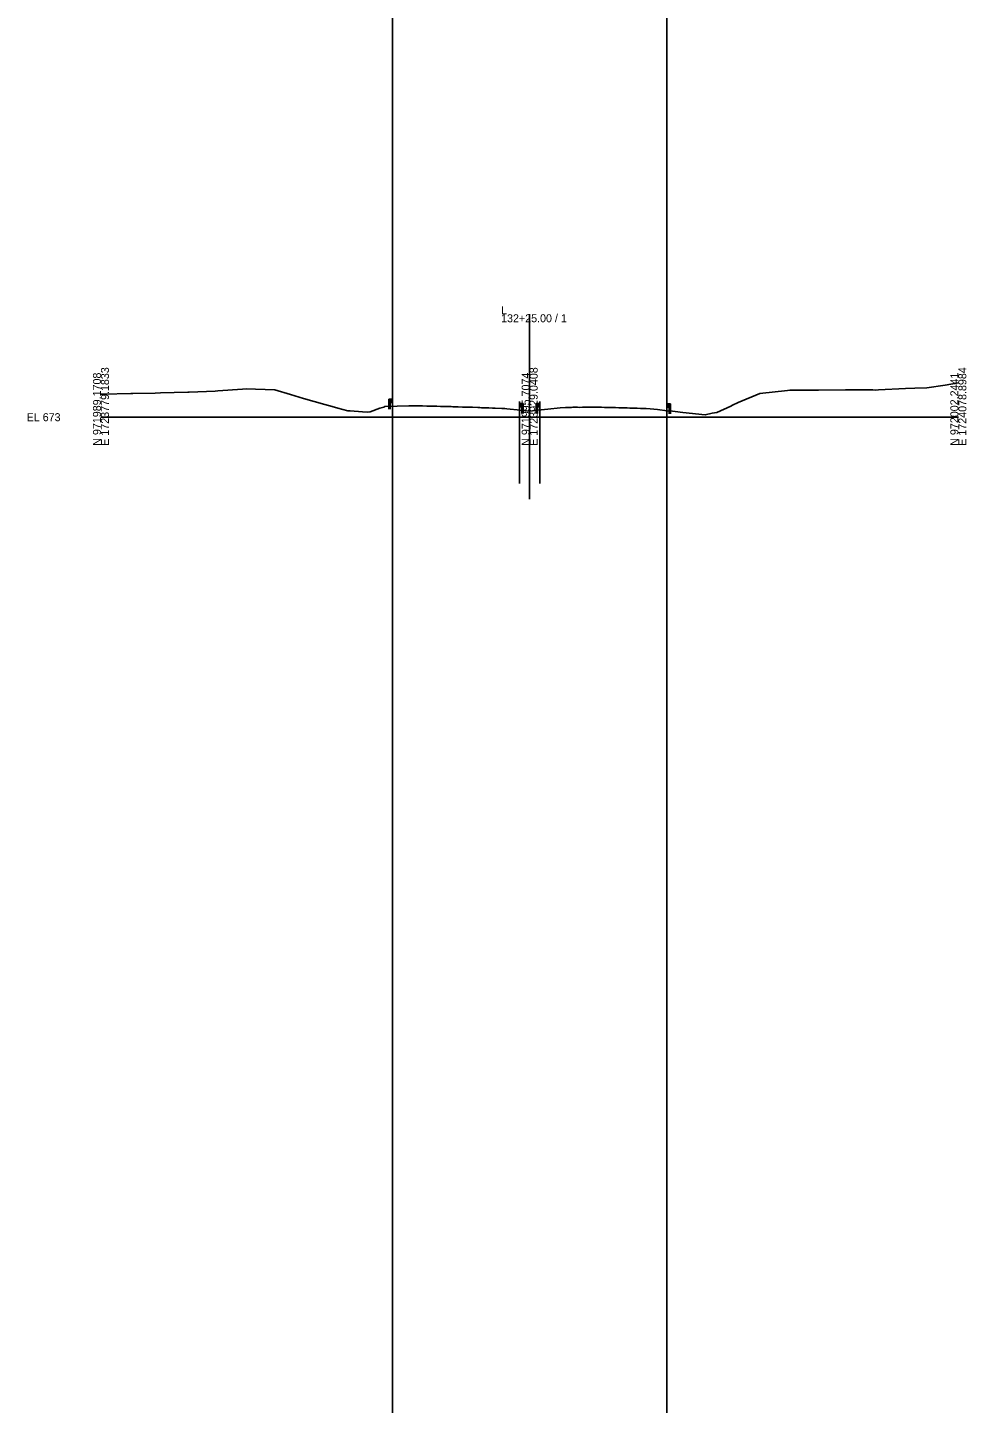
# Model space of a CAD drawing. Extents: x -26 to 303, y -29 to 15026.
# Drawn here: x -25.7 to 302.8, y 11654.8 to 12136.4 of the extents above; entities that cross this region are included whole.
import ezdxf

# ---------------------------------------------------------------- set-up
doc = ezdxf.new("R2010")
doc.units = 0
for name, color, linetype in [('Exist Cross Section Cell', 7, 'Continuous'), ('Exist XS Center Line Elevation Label', 7, 'Continuous'), ('Exist XS Ground Line', 7, 'Continuous'), ('Scratch_Level_0', 7, 'Continuous'), ('Typical Guardrail CELL', 7, 'Continuous')]:
    doc.layers.add(name, color=color, linetype=linetype)

msp = doc.modelspace()

# ---------------------------------------------------------------- linework, layer by layer
at = {"layer": 'Exist Cross Section Cell'}
for p, q in [((150, 12000), (150, 12036.03)), ((0, 12000), (150, 12000)), ((150, 12000), (300, 12000))]:
    msp.add_line(p, q, dxfattribs=at)
at = {"layer": 'Exist XS Ground Line'}
msp.add_lwpolyline([(0, 12008.05), (0.83, 12008.09), (10.47, 12008.29), (10.84, 12008.3), (11.18, 12008.32), (18.94, 12008.47), (20.85, 12008.51), (30.36, 12008.8), (30.86, 12008.8), (39.95, 12009.17), (40.87, 12009.2), (49.54, 12009.79), (50.88, 12009.89), (54.12, 12009.84), (60.88, 12009.63), (66.37, 12007.96), (70.89, 12006.59), (78.31, 12004.44), (80.9, 12003.74), (82.92, 12003.19), (86.36, 12002.2), (87.18, 12002.19), (91.48, 12001.89), (93.39, 12001.82), (94.14, 12001.85), (97.6, 12003.12), (98.95, 12003.52), (99.33, 12003.75), (103.66, 12003.89), (107.69, 12004.01), (108.03, 12004.01), (108.59, 12004), (110.01, 12003.98), (111.38, 12003.99), (112.54, 12003.95), (114.04, 12003.91), (115.04, 12003.88), (116.13, 12003.86), (117.54, 12003.85), (118.83, 12003.8), (120.03, 12003.76), (121.23, 12003.73), (122.52, 12003.7), (123.1, 12003.68), (123.81, 12003.66), (125.02, 12003.62), (126.56, 12003.57), (127.51, 12003.55), (128.4, 12003.52), (130.02, 12003.46), (131.81, 12003.39), (132.52, 12003.36), (133.18, 12003.33), (135.26, 12003.24), (135.67, 12003.23), (136.99, 12003.18), (137.53, 12003.16), (137.97, 12003.14), (140.22, 12003.06), (141.31, 12003.03), (142.02, 12002.95), (143.13, 12002.83), (145.6, 12002.58), (150.07, 12002.12), (152.84, 12002.42), (156.41, 12002.77), (160.73, 12003.25), (162.53, 12003.43), (162.98, 12003.43), (163.56, 12003.44), (164.23, 12003.45), (164.62, 12003.45), (165.06, 12003.46), (166.78, 12003.46), (167.58, 12003.45), (168.46, 12003.46), (170.08, 12003.48), (171.59, 12003.47), (172.6, 12003.47), (173.69, 12003.47), (175.09, 12003.47), (176.21, 12003.45), (177.07, 12003.44), (177.59, 12003.42), (178.9, 12003.37), (180.07, 12003.34), (181.15, 12003.31), (182.57, 12003.28), (184.13, 12003.24), (185.06, 12003.21), (185.92, 12003.19), (187.58, 12003.14), (188.77, 12003.1), (189.32, 12003.09), (190.09, 12003.05), (190.76, 12003.02), (192.18, 12002.97), (194.77, 12002.67), (198.16, 12002.28), (199.93, 12002.09), (200.95, 12001.94), (203.61, 12001.66), (211.45, 12000.79), (213.9, 12001.36), (215.46, 12001.65), (220.36, 12003.92), (221.03, 12004.25), (222.96, 12005.11), (230.52, 12008.29), (240.24, 12009.4), (241.05, 12009.5), (241.35, 12009.52), (248.41, 12009.48), (251.06, 12009.47), (260.54, 12009.54), (261.06, 12009.54), (270.13, 12009.53), (271.07, 12009.51), (272.11, 12009.53), (281.46, 12010.09), (284.81, 12010.14), (288.96, 12010.33), (295.36, 12011.26), (300, 12012.01)], dxfattribs=at)
at = {"layer": 'Scratch_Level_0'}
for p, q in [((102, 15009.56), (102, -28.7)), ((198, 15009.56), (198, -28.7)), ((146.46, 12005.5), (146.46, 11976.8)), ((153.54, 12005.5), (153.54, 11976.8)), ((150, 12000), (150, 11971.3))]:
    msp.add_line(p, q, dxfattribs=at)
at = {"layer": 'Typical Guardrail CELL'}
for p, q in [((101.18, 12006.28), (100.68, 12006.28)), ((100.68, 12006.28), (100.68, 12003.79)), ((101.18, 12006.28), (101.18, 12003.79)), ((101.18, 12006.28), (101.68, 12006.28)), ((101.68, 12006.28), (101.68, 12005.12)), ((101.68, 12006.28), (101.97, 12006.08)), ((101.68, 12005.75), (101.97, 12005.95)), ((101.68, 12005.7), (101.68, 12005.75)), ((101.68, 12005.7), (101.68, 12005.65)), ((101.68, 12005.65), (101.97, 12005.45)), ((101.18, 12003.79), (100.68, 12003.79)), ((100.68, 12003.79), (100.68, 12002.78)), ((101.18, 12005.12), (101.68, 12005.12)), ((101.18, 12003.79), (101.18, 12002.78)), ((101.68, 12005.12), (101.97, 12005.32)), ((146.78, 12004.84), (146.49, 12004.64)), ((146.78, 12004.31), (146.49, 12004.51)), ((146.78, 12004.21), (146.49, 12004.01)), ((146.78, 12003.68), (146.49, 12003.88)), ((147.28, 12004.84), (146.78, 12004.84)), ((146.78, 12004.84), (146.78, 12003.68)), ((146.78, 12004.26), (146.78, 12004.31)), ((146.78, 12004.26), (146.78, 12004.21)), ((147.28, 12003.68), (146.78, 12003.68)), ((147.28, 12004.84), (147.28, 12002.35)), ((147.28, 12004.84), (147.78, 12004.84)), ((147.28, 12002.35), (147.78, 12002.35)), ((147.28, 12002.35), (147.28, 12001.35)), ((147.78, 12004.84), (147.78, 12002.35)), ((147.78, 12002.35), (147.78, 12001.35)), ((152.72, 12004.84), (152.22, 12004.84)), ((152.22, 12004.84), (152.22, 12002.35)), ((152.72, 12002.35), (152.22, 12002.35)), ((152.22, 12002.35), (152.22, 12001.34)), ((152.72, 12004.84), (152.72, 12002.35)), ((152.72, 12004.84), (153.22, 12004.84)), ((152.72, 12003.68), (153.22, 12003.68)), ((152.72, 12002.35), (152.72, 12001.34)), ((153.22, 12004.84), (153.22, 12003.68)), ((153.22, 12004.84), (153.51, 12004.63)), ((153.22, 12004.3), (153.51, 12004.51)), ((153.22, 12004.26), (153.22, 12004.3)), ((153.22, 12004.26), (153.22, 12004.21)), ((153.22, 12004.21), (153.51, 12004.01)), ((153.22, 12003.68), (153.51, 12003.88)), ((198.32, 12004.64), (198.03, 12004.44)), ((198.32, 12004.11), (198.03, 12004.31)), ((198.32, 12004.01), (198.03, 12003.81)), ((198.32, 12003.48), (198.03, 12003.68)), ((198.82, 12004.64), (198.32, 12004.64)), ((198.32, 12004.64), (198.32, 12003.48)), ((198.32, 12004.06), (198.32, 12004.11)), ((198.32, 12004.06), (198.32, 12004.01)), ((198.82, 12003.48), (198.32, 12003.48)), ((198.82, 12004.64), (198.82, 12002.16)), ((198.82, 12004.64), (199.32, 12004.64)), ((198.82, 12002.16), (199.32, 12002.16)), ((198.82, 12002.16), (198.82, 12001.15)), ((199.32, 12004.64), (199.32, 12002.16)), ((199.32, 12002.16), (199.32, 12001.15))]:
    msp.add_line(p, q, dxfattribs=at)
for centre, start, end in [((101.92, 12006.01), 304.9888, 54.997), ((101.92, 12005.39), 304.9634, 54.9941), ((146.54, 12004.57), 125.003, 235.0112), ((146.54, 12003.95), 125.0059, 235.0366), ((153.46, 12004.57), 304.9888, 54.997), ((153.46, 12003.94), 304.9634, 54.9941), ((198.08, 12004.37), 125.003, 235.0112), ((198.08, 12003.75), 125.0059, 235.0366)]:
    msp.add_arc(centre, 0.0776, start, end, dxfattribs=at)

# ---------------------------------------------------------------- texts
at = {"layer": 'Exist Cross Section Cell'}
for s, p in [('132+25.00 / 1', (140, 12033.23)), ('L', (140, 12036.03)), ('EL 673', (-26, 11998.6))]:
    msp.add_text(s, height=2.8, dxfattribs=at).set_placement(p)
for s, p in [('N 971989.1708', (0, 11990)), ('E 1723779.1833', (2.8, 11990)), ('N 971995.7074', (150, 11990)), ('E 1723929.0408', (152.8, 11990)), ('N 972002.2441', (300, 11990)), ('E 1724078.8984', (302.8, 11990))]:
    msp.add_text(s, height=2.8, rotation=90, dxfattribs=at).set_placement(p)
at = {"layer": 'Exist XS Center Line Elevation Label'}
msp.add_text('675.12', height=0.18, dxfattribs=at).set_placement((149.64, 12001.63))

doc.saveas('drawing.dxf')
